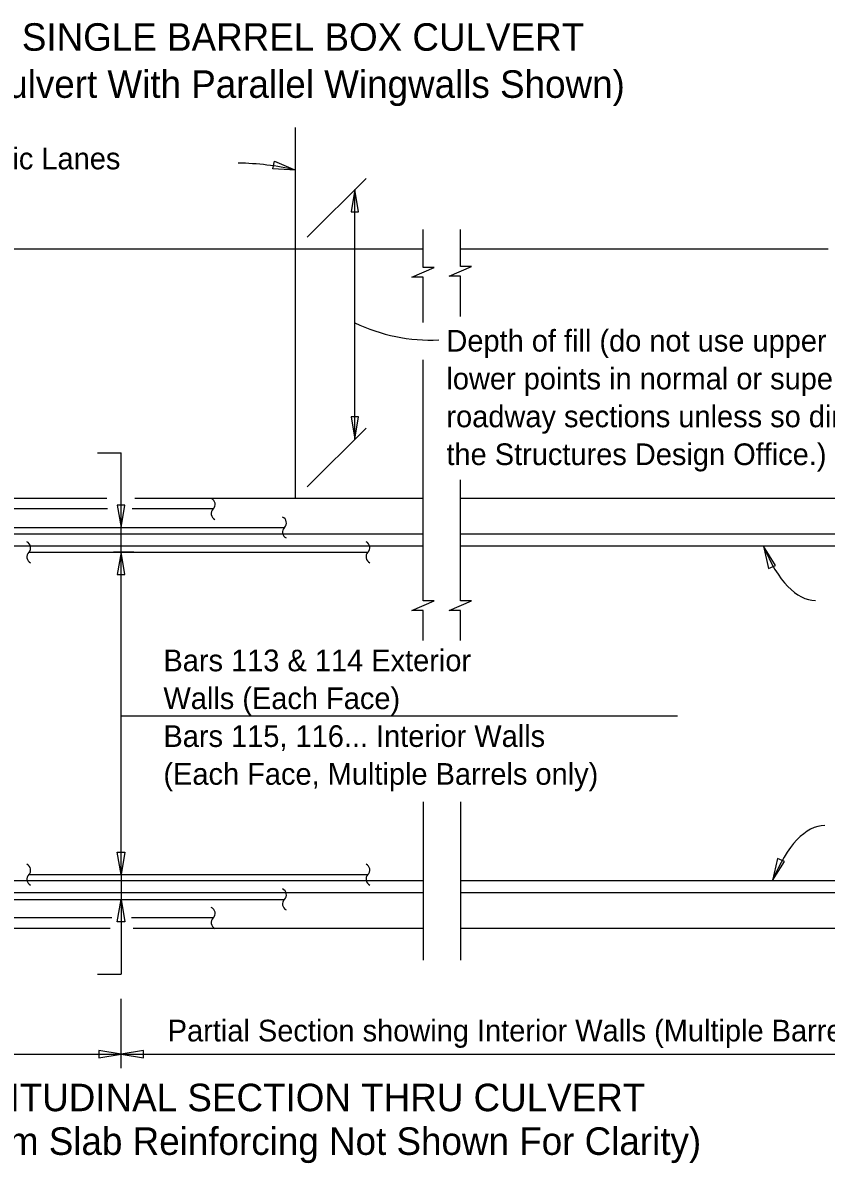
# Model space of a CAD drawing. Extents: x 0 to 221, y -2 to 90.
# Drawn here: x 54.52 to 76.95, y 7.04 to 38.88 of the extents above; entities that cross this region are included whole.
import ezdxf

# ---------------------------------------------------------------- set-up
doc = ezdxf.new("R2010")
doc.units = 0
for name, color, linetype in [('AdhocPoint_dp', 7, 'Continuous'), ('CL_Major', 7, 'Continuous'), ('Leader', 7, 'Continuous'), ('Miscellaneous', 7, 'Continuous'), ('PlotBorder_dp', 7, 'Continuous'), ('Rebar', 7, 'Continuous'), ('Symbols', 7, 'Continuous'), ('WallConc', 7, 'Continuous'), ('WallConc_h', 7, 'Continuous')]:
    doc.layers.add(name, color=color, linetype=linetype)

msp = doc.modelspace()

# ---------------------------------------------------------------- linework, layer by layer
at = {"layer": 'CL_Major'}
msp.add_line((62.135, 25.598), (62.135, 35.95), dxfattribs=at)
at = {"layer": 'Leader'}
for centre, radius, start, end in [((60.437, 27.347), 7.613, 77.1126, 89.2787), ((65.896, 34.817), 4.799, 243.9889, 272.8175)]:
    msp.add_arc(centre, radius, start, end, dxfattribs=at)
for centre, major_axis, start_param, end_param in [((76.665, 29.121), (0.017, 6.368), 2.439086, 3.141593), ((76.928, 10.099), (0.017, -6.368), 3.141593, 3.849934)]:
    msp.add_ellipse(centre, major_axis=major_axis, ratio=0.35421, start_param=start_param, end_param=end_param, dxfattribs=at)
at = {"layer": 'Miscellaneous'}
for p, q in [((48.416, 32.565), (65.695, 32.565)), ((66.736, 32.565), (76.999, 32.565))]:
    msp.add_line(p, q, dxfattribs=at)
at = {"layer": 'PlotBorder_dp'}
for p, q in [((62.464, 32.893), (64.103, 34.532)), ((63.791, 27.254), (63.791, 34.22)), ((62.464, 25.927), (64.103, 27.565)), ((56.613, 26.874), (57.267, 26.874)), ((57.267, 24.79), (57.267, 26.874)), ((57.267, 24.098), (57.267, 24.79)), ((57.624, 24.098), (57.056, 24.098)), ((57.267, 15.098), (57.267, 24.098)), ((57.267, 19.53), (72.799, 19.53)), ((65.695, 17.131), (65.695, 12.709)), ((66.736, 17.131), (66.736, 12.709)), ((57.267, 15.098), (57.267, 14.406)), ((57.267, 14.406), (57.267, 12.322)), ((56.613, 12.322), (57.267, 12.322)), ((57.267, 9.693), (57.267, 11.634)), ((36.523, 10.087), (57.267, 10.087)), ((57.267, 10.087), (88.109, 10.087))]:
    msp.add_line(p, q, dxfattribs=at)
for points in [[(62.135, 34.768), (61.503, 34.805), (61.55, 35.011)], [(63.791, 34.22), (63.685, 33.596), (63.897, 33.596)], [(63.791, 27.254), (63.897, 27.878), (63.685, 27.878)], [(57.267, 24.79), (57.373, 25.414), (57.161, 25.414)], [(75.195, 24.265), (75.336, 23.647), (75.532, 23.728)], [(57.267, 24.098), (57.161, 23.473), (57.373, 23.473)], [(57.267, 15.098), (57.161, 15.723), (57.373, 15.723)], [(75.448, 14.931), (75.783, 15.469), (75.587, 15.549)], [(57.267, 14.406), (57.373, 13.781), (57.161, 13.781)], [(57.267, 10.087), (56.642, 10.193), (56.642, 9.981)], [(57.267, 10.087), (57.892, 9.981), (57.892, 10.193)]]:
    msp.add_lwpolyline(points, close=True, dxfattribs=at)
for centre, start, end in [((59.712, 25.435), 314.1793, 65.9065), ((59.961, 25.178), 134.1793, 245.9065), ((61.701, 24.918), 314.1793, 65.9065), ((61.95, 24.661), 134.1793, 245.9065), ((54.565, 24.226), 314.1793, 65.9065), ((64.032, 24.226), 314.1793, 65.9065), ((54.814, 23.97), 134.1793, 245.9065), ((64.282, 23.97), 134.1793, 245.9065), ((54.565, 15.226), 314.1793, 65.9065), ((64.032, 15.226), 314.1793, 65.9065), ((54.814, 14.97), 134.1793, 245.9065), ((64.282, 14.97), 134.1793, 245.9065), ((61.701, 14.535), 314.1793, 65.9065), ((61.95, 14.278), 134.1793, 245.9065), ((59.712, 14.018), 314.1793, 65.9065), ((59.961, 13.761), 134.1793, 245.9065)]:
    msp.add_arc(centre, 0.179, start, end, dxfattribs=at)
at = {"layer": 'Rebar'}
for p, q in [((56.892, 25.306), (48.839, 25.306)), ((59.836, 25.306), (57.578, 25.306)), ((51.597, 24.79), (61.826, 24.79)), ((54.689, 24.098), (64.157, 24.098)), ((54.689, 15.098), (64.157, 15.098)), ((51.597, 14.406), (61.826, 14.406)), ((57.01, 13.89), (48.839, 13.89)), ((59.836, 13.89), (57.555, 13.89))]:
    msp.add_line(p, q, dxfattribs=at)
at = {"layer": 'Symbols'}
for points in [[(65.695, 30.514), (65.695, 31.773), (65.385, 31.773), (66.005, 32.043), (65.695, 32.043), (65.695, 33.107)], [(66.736, 30.683), (66.736, 31.8), (66.426, 31.8), (67.046, 32.07), (66.736, 32.07), (66.736, 33.107)], [(65.695, 21.637), (65.695, 22.473), (65.385, 22.473), (66.005, 22.743), (65.695, 22.743), (65.695, 29.472)], [(66.736, 21.637), (66.736, 22.473), (66.426, 22.473), (67.046, 22.743), (66.736, 22.743), (66.736, 26.118)]]:
    msp.add_lwpolyline(points, dxfattribs=at)
at = {"layer": 'WallConc'}
for p, q in [((56.873, 25.598), (27.165, 25.598)), ((65.695, 25.598), (57.647, 25.598)), ((98.25, 25.598), (66.736, 25.598)), ((65.695, 24.598), (53.866, 24.598)), ((99, 24.598), (66.736, 24.598)), ((53.808, 14.598), (65.695, 14.598)), ((66.736, 14.598), (100.937, 14.598)), ((56.966, 13.598), (25.415, 13.598)), ((65.695, 13.598), (57.608, 13.598)), ((100, 13.598), (66.736, 13.598))]:
    msp.add_line(p, q, dxfattribs=at)
at = {"layer": 'WallConc_h'}
for p, q in [((65.695, 24.265), (53.792, 24.265)), ((99.5, 24.265), (66.736, 24.265)), ((53.808, 14.931), (65.695, 14.931)), ((66.736, 14.931), (99.5, 14.931))]:
    msp.add_line(p, q, dxfattribs=at)

# ---------------------------------------------------------------- texts
at = {"layer": 'AdhocPoint_dp'}
for s, height, p in [('SINGLE BARREL BOX CULVERT', 0.768, (54.497, 38.097)), ('(Skewed Culvert With Parallel Wingwalls Shown)', 0.768, (49.067, 36.782)), ('Center of Traffic Lanes', 0.6048, (49.021, 34.787)), ('Depth of fill (do not use upper or', 0.6048, (66.347, 29.699)), ('lower points in normal or superelevated', 0.6048, (66.347, 28.643)), ('roadway sections unless so directed by', 0.6048, (66.347, 27.587)), ('the Structures Design Office.)', 0.6048, (66.347, 26.531)), ('Bars 113 & 114 Exterior', 0.6048, (58.449, 20.775)), ('Walls (Each Face)', 0.6048, (58.449, 19.719)), ('Bars 115, 116... Interior Walls', 0.6048, (58.449, 18.663)), ('(Each Face, Multiple Barrels only)', 0.6048, (58.449, 17.607)), ('Partial Section showing Interior Walls (Multiple Barrels only)', 0.6048, (58.569, 10.442)), ('LONGITUDINAL SECTION THRU CULVERT', 0.768, (51.242, 8.494)), ('(Transverse Top & Bottom Slab Reinforcing Not Shown For Clarity)', 0.768, (42.921, 7.275))]:
    msp.add_text(s, height=height, dxfattribs=at).set_placement(p)

doc.saveas('drawing.dxf')
